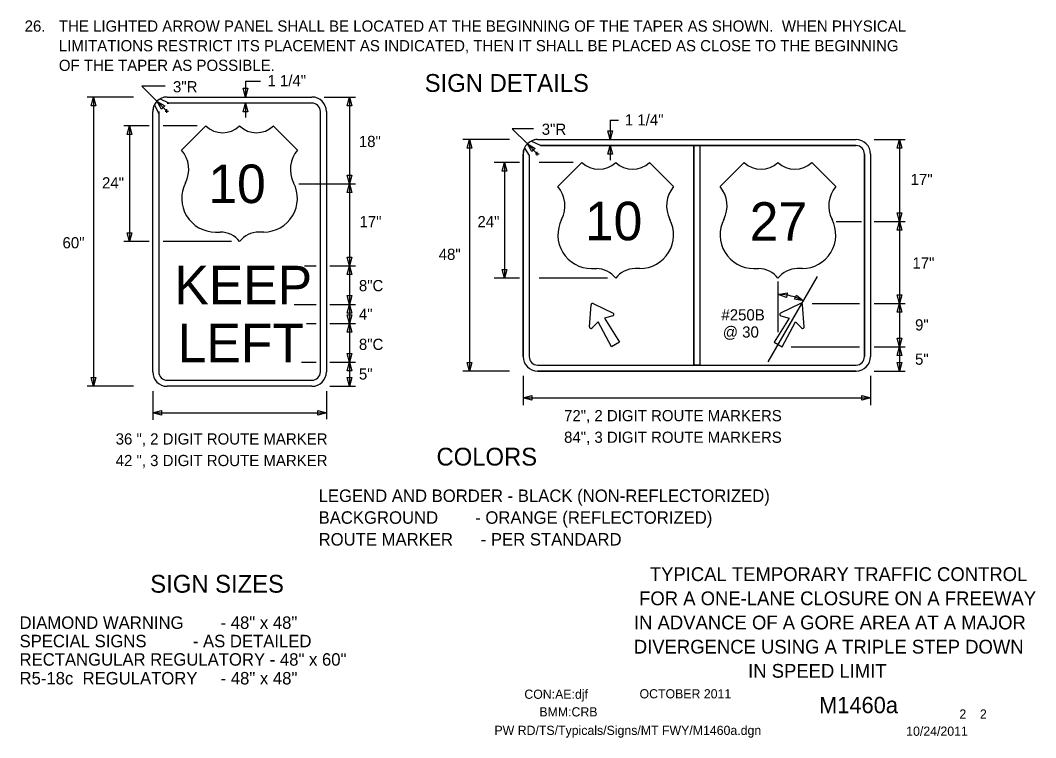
# Model space of a CAD drawing. Extents: x 16440 to 18464, y 5737 to 6974.
# Drawn here: x 17780 to 18464, y 5932 to 6415 of the extents above; entities that cross this region are included whole.
import ezdxf

# ---------------------------------------------------------------- set-up
doc = ezdxf.new("R2010")
doc.units = 0
for name, color, linetype in [('BORDER', 7, 'Continuous'), ('BORDER_SIGNAL_WO', 7, 'Continuous'), ('TRAFFIC_SIGNS_PR', 7, 'Continuous'), ('TYPICAL_EX', 7, 'Continuous'), ('TYPICAL_TEXT_DIMEN_PR', 7, 'Continuous')]:
    doc.layers.add(name, color=color, linetype=linetype)

msp = doc.modelspace()

# ---------------------------------------------------------------- linework, layer by layer
at = {"layer": 'TRAFFIC_SIGNS_PR'}
for p, q in [((17880.31, 6359.64), (17874.21, 6362.38)), ((17879.1, 6363.7), (17976.6, 6363.7)), ((17871.52, 6360.08), (17870.52, 6358.57)), ((17870.55, 6358.5), (17873.42, 6352.46)), ((17976.6, 6359.64), (17879.1, 6359.64)), ((17869.35, 6178.45), (17869.35, 6353.95)), ((17873.42, 6353.95), (17873.42, 6178.45)), ((17982.29, 6178.45), (17982.29, 6353.95)), ((17986.35, 6353.95), (17986.35, 6178.45)), ((18130.58, 6330.95), (18124.35, 6333.97)), ((18128.63, 6335), (18343.13, 6335)), ((18128.63, 6335), (18343.13, 6335)), ((18119.8, 6329.26), (18122.93, 6324.21)), ((18130.56, 6330.94), (18233.85, 6330.94)), ((18343.13, 6330.94), (18130.56, 6330.94)), ((18233.85, 6330.94), (18233.85, 6183.06)), ((18237.91, 6330.94), (18237.91, 6183.06)), ((18237.91, 6330.94), (18343.13, 6330.94)), ((18118.88, 6325.25), (18118.88, 6188.75)), ((18118.88, 6188.75), (18118.88, 6325.25)), ((18122.94, 6324.2), (18122.94, 6188.75)), ((18122.94, 6324.2), (18122.94, 6188.75)), ((18348.81, 6325.25), (18348.81, 6279.5)), ((18348.81, 6188.75), (18348.81, 6325.25)), ((18352.88, 6325.25), (18352.88, 6188.75)), ((18352.88, 6325.25), (18352.88, 6188.75)), ((18348.81, 6279.5), (18348.81, 6188.75)), ((18166.14, 6224.44), (18179.46, 6218.08)), ((18305.61, 6224.44), (18292.3, 6218.08)), ((18163.48, 6208.86), (18164.63, 6223.57)), ((18308.27, 6208.86), (18307.12, 6223.57)), ((18128.63, 6183.06), (18343.13, 6183.06)), ((18128.63, 6179), (18343.13, 6179)), ((18343.13, 6179), (18128.63, 6179)), ((17879.1, 6172.76), (17976.6, 6172.76)), ((17976.6, 6168.7), (17879.1, 6168.7))]:
    msp.add_line(p, q, dxfattribs=at)
for points in [[(18130.56, 6330.94), (18130.55, 6330.94)], [(18122.93, 6324.21), (18122.94, 6324.2)], [(18179.29, 6216.11), (18173.57, 6214.54), (18183.79, 6198.37), (18178.39, 6195.25), (18169.49, 6212.19), (18165.27, 6208.02)], [(18292.46, 6216.11), (18298.18, 6214.54), (18287.96, 6198.37), (18293.36, 6195.25), (18302.26, 6212.19), (18306.48, 6208.02)]]:
    msp.add_lwpolyline(points, dxfattribs=at)
msp.add_lwpolyline([(18233.85, 6330.94), (18237.91, 6330.94), (18237.91, 6183.06), (18233.85, 6183.06)], close=True, dxfattribs=at)
for centre, radius, start, end in [((17879.1, 6353.95), 9.75, 90, 180), ((17878.52, 6356.12), 7.6, 85.58319, 124.53531), ((17976.6, 6353.95), 9.75, 0, 90), ((17876.39, 6354.54), 7.06, 145.86811, 184.82317), ((17879.71, 6364.06), 4.47, 262.2432, 277.7568), ((17976.6, 6353.95), 5.69, 0, 90), ((17867.96, 6353.2), 5.51, 352.24294, 7.75653), ((18128.63, 6325.25), 9.75, 90, 180), ((18128.63, 6325.25), 9.75, 90, 180), ((18127.95, 6328.43), 6.6, 84.11162, 123.06374), ((18343.13, 6325.25), 9.75, 0, 90), ((18343.13, 6325.25), 9.75, 0, 90), ((18125.01, 6325.95), 6.17, 147.60925, 186.56283), ((18129.57, 6338.12), 7.24, 277.81035, 278.05403), ((18343.13, 6325.25), 5.69, 0, 89.99421), ((18343.13, 6325.25), 5.69, 0, 90), ((18165.68, 6223.49), 1.06, 64.48226, 175.51774), ((18306.07, 6223.49), 1.06, 4.48226, 115.51774), ((18179, 6217.13), 1.06, 285.9885, 64.48226), ((18292.75, 6217.13), 1.06, 115.51774, 254.0115), ((18164.53, 6208.78), 1.06, 175.51775, 314.01151), ((18307.22, 6208.78), 1.06, 225.98849, 4.48225), ((18128.63, 6188.75), 9.75, 180, 270), ((18128.63, 6188.75), 9.75, 180, 270), ((18128.63, 6188.75), 5.69, 180, 270), ((18128.63, 6188.75), 5.69, 180, 270), ((18343.13, 6188.75), 9.75, 270, 0), ((18343.13, 6188.75), 5.69, 270, 0), ((18343.13, 6188.75), 9.75, 270, 0), ((18343.13, 6188.75), 5.69, 270, 0), ((17879.1, 6178.45), 9.75, 180, 270), ((17879.1, 6178.45), 5.69, 180, 270), ((17976.6, 6178.45), 5.69, 270, 0), ((17976.6, 6178.45), 9.75, 270, 0)]:
    msp.add_arc(centre, radius, start, end, dxfattribs=at)
at = {"layer": 'TYPICAL_EX'}
for p, q in [((17888.85, 6327.95), (17905.1, 6344.2)), ((17966.86, 6327.95), (17950.6, 6344.2)), ((18142.24, 6303.34), (18158.49, 6319.59)), ((18220.24, 6303.34), (18203.99, 6319.59)), ((18251.51, 6303.34), (18267.76, 6319.59)), ((18329.52, 6303.34), (18313.26, 6319.59)), ((17911.58, 6272.66), (17914.83, 6272.66)), ((17944.13, 6272.66), (17940.88, 6272.66)), ((18164.96, 6248.05), (18168.21, 6248.05)), ((18197.51, 6248.05), (18194.26, 6248.05)), ((18274.24, 6248.05), (18277.49, 6248.05)), ((18306.79, 6248.05), (18303.54, 6248.05))]:
    msp.add_line(p, q, dxfattribs=at)
for centre, radius, start, end in [((17916.48, 6356.03), 16.42, 226.14041, 313.85958), ((17939.23, 6356.04), 16.42, 226.14042, 313.85959), ((17873.45, 6314.94), 20.16, 333.09768, 40.19361), ((17982.26, 6314.94), 20.16, 139.80639, 206.90233), ((18169.86, 6331.42), 16.42, 226.14041, 313.85958), ((18192.61, 6331.43), 16.42, 226.14042, 313.85959), ((18279.14, 6331.42), 16.42, 226.14041, 313.85958), ((18301.89, 6331.43), 16.42, 226.14042, 313.85959), ((17911.62, 6295.38), 22.73, 152.6698, 269.90132), ((17944.09, 6295.38), 22.73, 270.09868, 27.3302), ((18126.84, 6290.33), 20.16, 333.09768, 40.19361), ((18235.64, 6290.33), 20.16, 139.80639, 206.90233), ((18236.11, 6290.33), 20.16, 333.09768, 40.19361), ((18344.92, 6290.33), 20.16, 139.80639, 206.90233), ((18165.01, 6270.77), 22.73, 152.6698, 269.90132), ((18197.47, 6270.77), 22.73, 270.09868, 27.3302), ((18274.28, 6270.77), 22.73, 152.6698, 269.90132), ((18306.75, 6270.77), 22.73, 270.09868, 27.3302), ((17914.87, 6256.38), 16.28, 37.1038, 90.13853), ((17940.84, 6256.38), 16.28, 89.86147, 142.8962), ((18168.26, 6231.77), 16.28, 37.1038, 90.13853), ((18194.22, 6231.77), 16.28, 89.86147, 142.8962), ((18277.53, 6231.77), 16.28, 37.1038, 90.13853), ((18303.5, 6231.77), 16.28, 89.86147, 142.8962)]:
    msp.add_arc(centre, radius, start, end, dxfattribs=at)
at = {"layer": 'TYPICAL_TEXT_DIMEN_PR'}
for p, q in [((17877.72, 6370.98), (17862.07, 6370.98)), ((17862.07, 6370.98), (17872.31, 6360.74)), ((17931.83, 6363.7), (17930.25, 6369.56)), ((17930.25, 6369.56), (17931.83, 6369.56)), ((17931.83, 6374.46), (17931.83, 6363.7)), ((17931.83, 6374.46), (17941.93, 6374.46)), ((17931.83, 6369.56), (17933.4, 6369.56)), ((17933.4, 6369.56), (17931.83, 6363.7)), ((17856.52, 6363.7), (17825.23, 6363.7)), ((17828, 6357.84), (17829.57, 6363.7)), ((17829.57, 6363.7), (17829.57, 6168.7)), ((17829.57, 6363.7), (17831.14, 6357.84)), ((17984.89, 6363.7), (18005.85, 6363.7)), ((18000.39, 6357.84), (18001.96, 6363.7)), ((18001.96, 6363.7), (18001.96, 6305.2)), ((18001.96, 6363.7), (18003.53, 6357.84)), ((17829.57, 6357.84), (17828, 6357.84)), ((17831.14, 6357.84), (17829.57, 6357.84)), ((17872.31, 6360.74), (17878.86, 6354.19)), ((17875.34, 6355.49), (17872.31, 6360.74)), ((17872.31, 6360.74), (17877.56, 6357.71)), ((17876.45, 6356.6), (17875.34, 6355.49)), ((17877.56, 6357.71), (17876.45, 6356.6)), ((17877.65, 6354.19), (17880.07, 6354.19)), ((17878.86, 6352.98), (17878.86, 6355.4)), ((17930.3, 6353.77), (17931.87, 6359.64)), ((17931.87, 6359.64), (17931.87, 6349.89)), ((17931.87, 6359.64), (17933.44, 6353.77)), ((18001.96, 6357.84), (18000.39, 6357.84)), ((18003.53, 6357.84), (18001.96, 6357.84)), ((17931.87, 6353.77), (17930.3, 6353.77)), ((17933.44, 6353.77), (17931.87, 6353.77)), ((18177.48, 6348.15), (18177.48, 6335)), ((18177.48, 6348.15), (18183.01, 6348.15)), ((17866.98, 6344.2), (17849.85, 6344.2)), ((17852.18, 6338.34), (17853.75, 6344.2)), ((17853.75, 6344.2), (17853.75, 6266.2)), ((17853.75, 6344.2), (17855.32, 6338.34)), ((17899.22, 6344.2), (17876.34, 6344.2)), ((18125.77, 6342.28), (18111.59, 6342.28)), ((18111.59, 6342.28), (18121.74, 6332.14)), ((18177.48, 6335), (18175.91, 6340.86)), ((18175.91, 6340.86), (18177.48, 6340.86)), ((18177.48, 6340.86), (18179.05, 6340.86)), ((18179.05, 6340.86), (18177.48, 6335)), ((17853.75, 6338.34), (17852.18, 6338.34)), ((17855.32, 6338.34), (17853.75, 6338.34)), ((18109.64, 6335), (18078.35, 6335)), ((18081.12, 6329.14), (18082.69, 6335)), ((18082.69, 6335), (18082.69, 6179)), ((18082.69, 6335), (18084.26, 6329.14)), ((18355.25, 6335), (18376.21, 6335)), ((18370.74, 6329.14), (18372.31, 6335)), ((18372.31, 6335), (18372.31, 6279.75)), ((18372.31, 6335), (18373.88, 6329.14)), ((18082.69, 6329.14), (18081.12, 6329.14)), ((18084.26, 6329.14), (18082.69, 6329.14)), ((18121.74, 6332.14), (18128.39, 6325.49)), ((18124.77, 6326.88), (18121.74, 6332.14)), ((18121.74, 6332.14), (18126.99, 6329.1)), ((18125.88, 6327.99), (18124.77, 6326.88)), ((18126.99, 6329.1), (18125.88, 6327.99)), ((18175.96, 6325.07), (18177.53, 6330.94)), ((18175.96, 6325.07), (18177.53, 6330.94)), ((18177.53, 6330.94), (18177.53, 6321.19)), ((18177.53, 6330.94), (18179.1, 6325.07)), ((18177.53, 6330.94), (18179.1, 6325.07)), ((18372.31, 6329.14), (18370.74, 6329.14)), ((18373.88, 6329.14), (18372.31, 6329.14)), ((18127.18, 6325.49), (18129.6, 6325.49)), ((18128.39, 6324.28), (18128.39, 6326.7)), ((18177.53, 6325.07), (18175.96, 6325.07)), ((18177.53, 6325.07), (18175.96, 6325.07)), ((18179.1, 6325.07), (18177.53, 6325.07)), ((18179.1, 6325.07), (18177.53, 6325.07)), ((18116.5, 6319.59), (18099.38, 6319.59)), ((18104.67, 6313.73), (18106.24, 6319.59)), ((18106.24, 6313.73), (18104.67, 6313.73)), ((18106.24, 6319.59), (18106.24, 6241.59)), ((18106.24, 6319.59), (18107.81, 6313.73)), ((18107.81, 6313.73), (18106.24, 6313.73)), ((18152.6, 6319.59), (18129.73, 6319.59)), ((18001.96, 6305.2), (18000.39, 6311.06)), ((18000.39, 6311.06), (18001.96, 6311.06)), ((18001.96, 6311.06), (18003.53, 6311.06)), ((18003.53, 6311.06), (18001.96, 6305.2)), ((17967.74, 6305.2), (18005.85, 6305.2)), ((18000.39, 6299.34), (18001.96, 6305.2)), ((18001.96, 6305.2), (18001.96, 6249.95)), ((18001.96, 6305.2), (18003.53, 6299.34)), ((18001.96, 6299.34), (18000.39, 6299.34)), ((18003.53, 6299.34), (18001.96, 6299.34)), ((18329.69, 6279.75), (18346.84, 6279.75)), ((18355.25, 6279.75), (18376.21, 6279.75)), ((18372.31, 6279.75), (18370.74, 6285.61)), ((18370.74, 6285.61), (18372.31, 6285.61)), ((18370.74, 6273.89), (18372.31, 6279.75)), ((18372.31, 6285.61), (18373.88, 6285.61)), ((18373.88, 6285.61), (18372.31, 6279.75)), ((18372.31, 6279.75), (18372.31, 6224.5)), ((18372.31, 6279.75), (18373.88, 6273.89)), ((18372.31, 6273.89), (18370.74, 6273.89)), ((18373.88, 6273.89), (18372.31, 6273.89)), ((17866.98, 6266.2), (17849.85, 6266.2)), ((17853.75, 6266.2), (17852.18, 6272.06)), ((17852.18, 6272.06), (17853.75, 6272.06)), ((17853.75, 6272.06), (17855.32, 6272.06)), ((17855.32, 6272.06), (17853.75, 6266.2)), ((17922.35, 6266.2), (17876.34, 6266.2)), ((18001.96, 6249.95), (18000.39, 6255.81)), ((18000.39, 6255.81), (18001.96, 6255.81)), ((18001.96, 6255.81), (18003.53, 6255.81)), ((18003.53, 6255.81), (18001.96, 6249.95)), ((17971.68, 6249.95), (17979.36, 6249.95)), ((17988.73, 6249.95), (18005.85, 6249.95)), ((18000.39, 6244.09), (18001.96, 6249.95)), ((18001.96, 6249.95), (18001.96, 6223.95)), ((18001.96, 6249.95), (18003.53, 6244.09)), ((18106.24, 6241.59), (18104.67, 6247.45)), ((18104.67, 6247.45), (18106.24, 6247.45)), ((18106.24, 6247.45), (18107.81, 6247.45)), ((18107.81, 6247.45), (18106.24, 6241.59)), ((18001.96, 6244.09), (18000.39, 6244.09)), ((18003.53, 6244.09), (18001.96, 6244.09)), ((18116.5, 6241.59), (18099.38, 6241.59)), ((18175.73, 6241.59), (18129.73, 6241.59)), ((18283.91, 6185.1), (18317.15, 6242.69)), ((18290.67, 6205.25), (18290.67, 6239.25)), ((18290.69, 6230.69), (18296.69, 6231.65)), ((18296.69, 6231.65), (18296.52, 6230.09)), ((18001.96, 6223.95), (18000.39, 6229.81)), ((18000.39, 6229.81), (18001.96, 6229.81)), ((18001.96, 6229.81), (18003.53, 6229.81)), ((18003.53, 6229.81), (18001.96, 6223.95)), ((18296.36, 6228.53), (18290.69, 6230.69)), ((18296.52, 6230.09), (18296.36, 6228.53)), ((18301.68, 6227.37), (18302.36, 6228.78)), ((18307.64, 6226.24), (18301.68, 6227.37)), ((18302.36, 6228.78), (18303.04, 6230.2)), ((18303.04, 6230.2), (18307.64, 6226.24)), ((18313.62, 6224.5), (18345.49, 6224.5)), ((18355.25, 6224.5), (18376.21, 6224.5)), ((18372.31, 6224.5), (18370.74, 6230.36)), ((18370.74, 6230.36), (18372.31, 6230.36)), ((18370.74, 6218.64), (18372.31, 6224.5)), ((18372.31, 6230.36), (18373.88, 6230.36)), ((18373.88, 6230.36), (18372.31, 6224.5)), ((18372.31, 6224.5), (18372.31, 6195.25)), ((18372.31, 6224.5), (18373.88, 6218.64)), ((17964.66, 6223.95), (17979.36, 6223.95)), ((17988.73, 6223.95), (18005.85, 6223.95)), ((18000.39, 6218.09), (18001.96, 6223.95)), ((18001.96, 6218.09), (18000.39, 6218.09)), ((18001.96, 6223.95), (18001.96, 6210.95)), ((18001.96, 6223.95), (18003.53, 6218.09)), ((18003.53, 6218.09), (18001.96, 6218.09)), ((18372.31, 6218.64), (18370.74, 6218.64)), ((18373.88, 6218.64), (18372.31, 6218.64)), ((17973.02, 6210.95), (17979.36, 6210.95)), ((17988.73, 6210.95), (18005.85, 6210.95)), ((18001.96, 6210.95), (18000.39, 6216.81)), ((18000.39, 6216.81), (18001.96, 6216.81)), ((18000.39, 6205.09), (18001.96, 6210.95)), ((18001.96, 6216.81), (18003.53, 6216.81)), ((18003.53, 6216.81), (18001.96, 6210.95)), ((18001.96, 6210.95), (18001.96, 6184.95)), ((18001.96, 6210.95), (18003.53, 6205.09)), ((18001.96, 6205.09), (18000.39, 6205.09)), ((18003.53, 6205.09), (18001.96, 6205.09)), ((18372.31, 6195.25), (18370.74, 6201.11)), ((18370.74, 6201.11), (18372.31, 6201.11)), ((18372.31, 6201.11), (18373.88, 6201.11)), ((18373.88, 6201.11), (18372.31, 6195.25)), ((18001.96, 6184.95), (18000.39, 6190.81)), ((18000.39, 6190.81), (18001.96, 6190.81)), ((18001.96, 6190.81), (18003.53, 6190.81)), ((18003.53, 6190.81), (18001.96, 6184.95)), ((18299.48, 6195.25), (18345.49, 6195.25)), ((18355.25, 6195.25), (18376.21, 6195.25)), ((18370.74, 6189.39), (18372.31, 6195.25)), ((18372.31, 6195.25), (18372.31, 6179)), ((18372.31, 6195.25), (18373.88, 6189.39)), ((17969.52, 6184.95), (17979.36, 6184.95)), ((17988.73, 6184.95), (18005.85, 6184.95)), ((18000.39, 6179.09), (18001.96, 6184.95)), ((18001.96, 6184.95), (18001.96, 6168.7)), ((18001.96, 6184.95), (18003.53, 6179.09)), ((18082.69, 6179), (18081.12, 6184.86)), ((18081.12, 6184.86), (18082.69, 6184.86)), ((18082.69, 6184.86), (18084.26, 6184.86)), ((18084.26, 6184.86), (18082.69, 6179)), ((18372.31, 6189.39), (18370.74, 6189.39)), ((18372.31, 6179), (18370.74, 6184.86)), ((18370.74, 6184.86), (18372.31, 6184.86)), ((18373.88, 6189.39), (18372.31, 6189.39)), ((18372.31, 6184.86), (18373.88, 6184.86)), ((18373.88, 6184.86), (18372.31, 6179)), ((18001.96, 6179.09), (18000.39, 6179.09)), ((18003.53, 6179.09), (18001.96, 6179.09)), ((18109.64, 6179), (18078.35, 6179)), ((18355.25, 6179), (18372.38, 6179)), ((18355.25, 6179), (18376.21, 6179)), ((18355.25, 6179), (18372.38, 6179)), ((17829.57, 6168.7), (17828, 6174.56)), ((17828, 6174.56), (17829.57, 6174.56)), ((17829.57, 6174.56), (17831.14, 6174.56)), ((17831.14, 6174.56), (17829.57, 6168.7)), ((18001.96, 6168.7), (18000.39, 6174.56)), ((18000.39, 6174.56), (18001.96, 6174.56)), ((18001.96, 6174.56), (18003.53, 6174.56)), ((18003.53, 6174.56), (18001.96, 6168.7)), ((18118.88, 6175.65), (18118.88, 6156.09)), ((18352.88, 6175.65), (18352.88, 6156.09)), ((17856.52, 6168.7), (17825.23, 6168.7)), ((17869.35, 6165.35), (17869.35, 6146)), ((17986.35, 6165.35), (17986.35, 6146.46)), ((17988.73, 6168.7), (18005.85, 6168.7)), ((18118.88, 6161.03), (18124.74, 6162.6)), ((18118.88, 6161.03), (18352.88, 6161.03)), ((18124.74, 6159.46), (18118.88, 6161.03)), ((18124.74, 6162.6), (18124.74, 6161.03)), ((18124.74, 6161.03), (18124.74, 6159.46)), ((18347.01, 6161.03), (18347.01, 6162.6)), ((18347.01, 6162.6), (18352.88, 6161.03)), ((18352.88, 6161.03), (18347.01, 6159.46)), ((18347.01, 6159.46), (18347.01, 6161.03)), ((17869.35, 6150.73), (17875.22, 6152.3)), ((17869.35, 6150.73), (17986.35, 6150.73)), ((17875.22, 6149.15), (17869.35, 6150.73)), ((17875.22, 6152.3), (17875.22, 6150.73)), ((17875.22, 6150.73), (17875.22, 6149.15)), ((17980.49, 6150.73), (17980.49, 6152.3)), ((17980.49, 6152.3), (17986.35, 6150.73)), ((17986.35, 6150.73), (17980.49, 6149.15)), ((17980.49, 6149.15), (17980.49, 6150.73))]:
    msp.add_line(p, q, dxfattribs=at)
msp.add_arc((18290.86, 6196.25), 34.39, 60.74521, 90.32117, dxfattribs=at)

# ---------------------------------------------------------------- texts
at = {"layer": 'BORDER'}
for s, p in [('TYPICAL TEMPORARY TRAFFIC CONTROL', (18204.21, 6037.44)), ('FOR A ONE-LANE CLOSURE ON A FREEWAY', (18196.99, 6021.14)), ('IN ADVANCE OF A GORE AREA AT A MAJOR', (18193.54, 6004.84)), ('DIVERGENCE USING A TRIPLE STEP DOWN ', (18193.42, 5988.54)), ('IN SPEED LIMIT', (18270.42, 5972.24))]:
    msp.add_text(s, height=9.3, dxfattribs=at).set_placement(p)
at = {"layer": 'BORDER_SIGNAL_WO'}
for s, height, p in [('CON:AE:djf  ', 6.2, (18119.69, 5958.06)), ('    OCTOBER 2011    ', 6.2, (18188.08, 5958.34)), ('    M1460a   ', 11, (18301.86, 5948.38)), ('BMM:CRB   ', 6.2, (18129.81, 5946.17)), (' 2    2 ', 6.2, (18410.45, 5944.7)), ('PW RD/TS/Typicals/Signs/MT FWY/M1460a.dgn      ', 6.2, (18099.55, 5933.71)), ('10/24/2011    ', 6.2, (18376.93, 5933.13))]:
    msp.add_text(s, height=height, dxfattribs=at).set_placement(p)
at = {"layer": 'TRAFFIC_SIGNS_PR'}
for s, p in [('10', (17906.83, 6292.2)), ('10', (18160.48, 6267.13)), ('27', (18271.48, 6266.77)), ('KEEP', (17883.96, 6223.95)), ('LEFT', (17886.19, 6184.95))]:
    msp.add_text(s, height=26, dxfattribs=at).set_placement(p)
at = {"layer": 'TYPICAL_TEXT_DIMEN_PR'}
for s, height, p in [('26.', 7.56, (17783.08, 6407.74)), ('THE LIGHTED ARROW PANEL SHALL BE LOCATED AT THE BEGINNING OF THE TAPER AS SHOWN.  WHEN PHYSICAL', 7.56, (17806.13, 6407.74)), ('LIMITATIONS RESTRICT ITS PLACEMENT AS INDICATED, THEN IT SHALL BE PLACED AS CLOSE TO THE BEGINNING', 7.56, (17806.13, 6394.51)), ('OF THE TAPER AS POSSIBLE.', 7.56, (17806.13, 6381.28)), ('1 1/4"', 7.55, (17946.63, 6370.95)), ('SIGN DETAILS', 12, (18052.58, 6367.17)), ('3"R', 7.55, (17882.99, 6366.86)), ('1 1/4"', 7.55, (18187.41, 6344.57)), ('3"R', 7.55, (18131.41, 6338.2)), ('18"', 7.55, (18008.2, 6329.97)), ('24"', 7.55, (17835.2, 6302.08)), ('17"', 7.55, (18379.89, 6304.36)), ('17"', 7.55, (18008.65, 6275.92)), ('24"', 7.55, (18088.1, 6275.92)), ('60"', 7.55, (17808.6, 6261.71)), ('48"', 7.55, (18061.99, 6253.9)), ('17"', 7.55, (18381.09, 6248)), ('8"C', 7.55, (18008.23, 6232.8)), ('4" ', 7.55, (18008.23, 6213.54)), ('#250B', 7.55, (18252.44, 6213.09)), ('9"', 7.55, (18382.87, 6206.34)), ('@ 30', 7.55, (18253.38, 6201.54)), ('8"C', 7.55, (18008.23, 6193.22)), ('5"', 7.55, (18382.87, 6183.24)), ('5" ', 7.55, (18008.23, 6173.24)), ('72", 2 DIGIT ROUTE MARKERS', 7.55, (18146.46, 6145.16)), ('36 ", 2 DIGIT ROUTE MARKER', 7.55, (17844.4, 6129.46)), ('84", 3 DIGIT ROUTE MARKERS', 7.55, (18146.46, 6130.61)), ('42 ", 3 DIGIT ROUTE MARKER', 7.55, (17844.4, 6114.91)), ('COLORS', 12, (18060.52, 6115.28)), ('LEGEND AND BORDER - BLACK (NON-REFLECTORIZED)', 8.4, (17981.1, 6090.75)), ('BACKGROUND        - ORANGE (REFLECTORIZED)', 8.4, (17981.1, 6076.05)), ('ROUTE MARKER      - PER STANDARD', 8.4, (17981.1, 6061.35)), ('SIGN SIZES', 12, (17867.69, 6029.59)), ('DIAMOND WARNING        - 48" x 48"', 8.4, (17779.65, 6005.19)), ('SPECIAL SIGNS          - AS DETAILED', 8.4, (17779.65, 5992.79)), ('RECTANGULAR REGULATORY - 48" x 60"', 8.4, (17779.65, 5980.39)), ('R5-18c  REGULATORY     - 48" x 48"', 8.4, (17779.65, 5967.74))]:
    msp.add_text(s, height=height, dxfattribs=at).set_placement(p)

doc.saveas('drawing.dxf')
